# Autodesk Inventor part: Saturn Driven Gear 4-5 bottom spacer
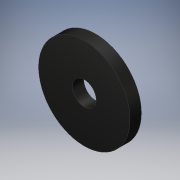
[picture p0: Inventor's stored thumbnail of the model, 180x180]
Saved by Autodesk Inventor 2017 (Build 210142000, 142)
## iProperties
Created: 2017-05
Part Number: Saturn Driven Gear 4-5 bottom spacer
Material: Generic
Document SubType Name: Modeling
Designer: Stan
Density: 1 g/cm^3
Appearance: Glossy - Black
Author: Stan
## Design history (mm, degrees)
sketch "Sketch1"
  geometry: C1 r 3.302 at (0, 0); C2 r 12.7 at (0, 0); 1 further point
  constraints: 2 centre point, 2 coincident
  dimensions: "d0" = 6.604 diameter of C1; "d1" = 25.4 diameter of C2
extrude "Extrusion1" new body sketch "Sketch1" distance "d2" = 3.175; taper "d3" = 0 deg
body "Solid1"
